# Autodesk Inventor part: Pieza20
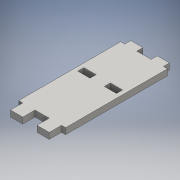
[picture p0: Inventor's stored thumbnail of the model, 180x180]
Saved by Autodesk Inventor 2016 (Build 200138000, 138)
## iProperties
Created: 2016-06
Part Number: Pieza20
Material: Genérico
Document SubType Name: Modeling
Designer: adm
Density: 1 g/cm^3
Appearance: Valor por defecto
Author: adm
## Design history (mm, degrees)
sketch "Boceto1"
  geometry: L1 (11.5, 25)-(11.5, -25); L2 (-11.5, -25)-(-11.5, 25); L3 (-11.5, 25)-(11.5, -25); L4 (11.5, 25)-(-11.5, -25); L5 (3.5, 25)-(3.5, 28); L6 (3.5, 28)-(9.5, 28); L7 (9.5, 28)-(9.5, 25); L8 (-3.5, 25)-(-3.5, 28); L9 (-3.5, 28)-(-9.5, 28); L10 (-9.5, 28)-(-9.5, 25); L11 (-11.5, 25)-(-9.5, 25); L12 (-3.5, 25)-(3.5, 25); L13 (9.5, 25)-(11.5, 25); L14 (9.5, -31)-(9.5, -25); L15 (3.5, -31)-(9.5, -31); L16 (-3.5, -25)-(-3.5, -31); L17 (-3.5, -31)-(-9.5, -31); L18 (-9.5, -31)-(-9.5, -25); L19 (3.5, -25)-(3.5, -31); L20 (-9.5, -25)-(-11.5, -25); L21 (11.5, -25)-(9.5, -25); L22 (3.5, -25)-(-3.5, -25); 1 further point
  constraints: 44 end point, 11 parallel, 5 horizontal, 4 vertical, 3 perpendicular, 2 horizontal alignment, 2 midpoint
  dimensions: "d0" = 50 distance of L1.start L1.end; "d1" = 23 distance of L1.end L2.start; "d2" = 3 distance of L6.end L7.end; "d3" = 2 distance between parallel lines of L7 L1; "d4" = 6 distance of L5.end L6.end; "d13" = 6 distance of L16.start L16.end; "d14" = 6 distance of L19.start L15.start
extrude "Extrusión1" new body sketch "Boceto1" distance "d5" = 3; taper "d6" = 0 deg
sketch "Boceto2"
  geometry: L1 (-9.5, 5)-(-3.5, 5); L2 (-3.5, 5)-(-3.5, 2); L3 (-3.5, 2)-(-9.5, 2); L4 (-9.5, 2)-(-9.5, 5); L5 (-11.5, 25)-(-11.5, -25) reference; L6 (3.5, 25)-(-3.5, 25) reference; L7 (0, 0)-(0, 10.364); L8 (9.5, 5)-(3.5, 5); L9 (3.5, 5)-(3.5, 2); L10 (3.5, 2)-(9.5, 2); L11 (9.5, 2)-(9.5, 5)
  constraints: 18 end point, 4 symmetric about line, 2 parallel, 1 horizontal, 1 perpendicular, 1 vertical
  dimensions: "d7" = 6 distance of L1.start L1.end; "d8" = 3 distance of L1.end L2.end; "d9" = 2 distance between parallel lines of L5 L4; "d10" = 20 distance between parallel lines of L1 L6
extrude "Extrusión2" cut sketch "Boceto2" distance "d11" = 10; taper "d12" = 0 deg
node "Sólido1"
